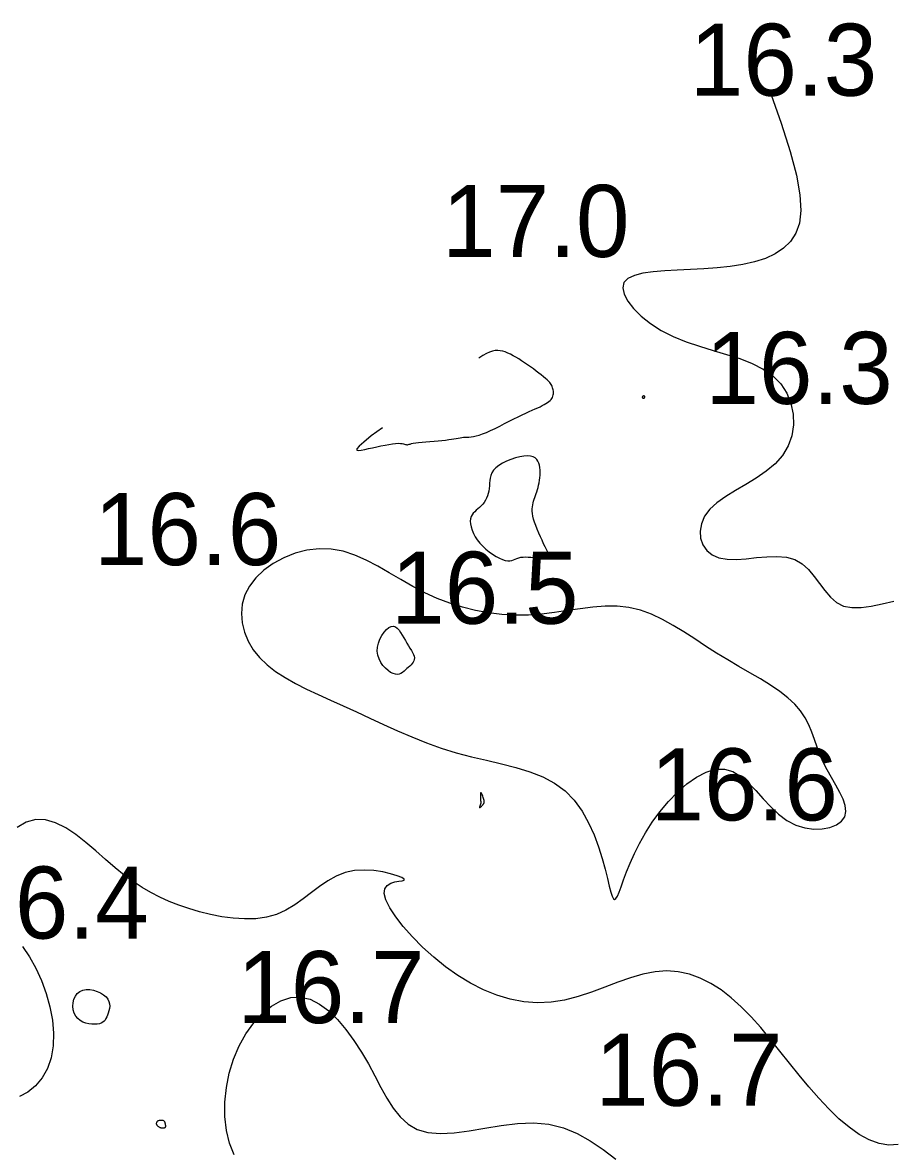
# Model space of a CAD drawing. Extents: x 3040093 to 3056816, y 408076 to 509144.
# Drawn here: x 3045706.9 to 3045767.3, y 434615.2 to 434693.7 of the extents above; entities that cross this region are included whole.
import ezdxf

# ---------------------------------------------------------------- set-up
doc = ezdxf.new("R2010")
doc.units = 0
doc.layers.add('V-CHAN-CONT-EL17', color=7, linetype='Continuous')
doc.layers.add('V-TOPO-SOUN-0610', color=7, linetype='Continuous')

msp = doc.modelspace()

# ---------------------------------------------------------------- linework, layer by layer
at = {"layer": 'V-CHAN-CONT-EL17'}
for points in [[(3045758.774, 434689.031), (3045759.617, 434686.678), (3045760.245, 434684.699), (3045760.671, 434683.056), (3045760.909, 434681.708), (3045760.975, 434680.615), (3045760.881, 434679.736), (3045760.643, 434679.032), (3045760.274, 434678.461), (3045759.788, 434677.99), (3045759.199, 434677.603), (3045758.52, 434677.292), (3045757.765, 434677.047), (3045756.947, 434676.861), (3045756.08, 434676.722), (3045755.177, 434676.623), (3045754.252, 434676.555), (3045753.319, 434676.507), (3045752.404, 434676.467), (3045751.53, 434676.421), (3045750.725, 434676.354), (3045750.013, 434676.254), (3045749.421, 434676.106), (3045748.974, 434675.897), (3045748.698, 434675.613), (3045748.611, 434675.245), (3045748.704, 434674.809), (3045748.961, 434674.323), (3045749.365, 434673.809), (3045749.899, 434673.286), (3045750.547, 434672.775), (3045751.293, 434672.295), (3045752.121, 434671.867), (3045753.011, 434671.504), (3045753.942, 434671.191), (3045754.89, 434670.906), (3045755.83, 434670.627), (3045756.738, 434670.332), (3045757.592, 434670.001), (3045758.365, 434669.61), (3045759.036, 434669.138), (3045759.582, 434668.571), (3045760, 434667.924), (3045760.287, 434667.219), (3045760.443, 434666.479), (3045760.465, 434665.726), (3045760.353, 434664.983), (3045760.105, 434664.273), (3045759.719, 434663.619), (3045759.201, 434663.036), (3045758.579, 434662.515), (3045757.889, 434662.043), (3045757.166, 434661.603), (3045756.447, 434661.182), (3045755.765, 434660.764), (3045755.158, 434660.334), (3045754.659, 434659.878), (3045754.298, 434659.386), (3045754.076, 434658.873), (3045753.986, 434658.36), (3045754.021, 434657.866), (3045754.176, 434657.413), (3045754.445, 434657.02), (3045754.821, 434656.709), (3045755.297, 434656.499), (3045755.866, 434656.403), (3045756.506, 434656.396), (3045757.194, 434656.446), (3045757.909, 434656.518), (3045758.626, 434656.581), (3045759.323, 434656.601), (3045759.978, 434656.545), (3045760.566, 434656.381), (3045761.073, 434656.086), (3045761.512, 434655.687), (3045761.907, 434655.22), (3045762.277, 434654.722), (3045762.645, 434654.23), (3045763.033, 434653.781), (3045763.462, 434653.412), (3045763.955, 434653.159), (3045764.526, 434653.048), (3045765.171, 434653.06), (3045765.878, 434653.161), (3045766.635, 434653.321), (3045767.433, 434653.508)], [(3045731.921, 434665.536), (3045731.154, 434664.964), (3045730.624, 434664.543), (3045730.3, 434664.252), (3045730.151, 434664.071), (3045730.147, 434663.979), (3045730.257, 434663.955), (3045730.449, 434663.978), (3045730.694, 434664.029), (3045730.963, 434664.088), (3045731.246, 434664.15), (3045731.537, 434664.214), (3045731.826, 434664.275), (3045732.109, 434664.331), (3045732.376, 434664.379), (3045732.622, 434664.418), (3045732.839, 434664.443), (3045733.021, 434664.453), (3045733.171, 434664.451), (3045733.292, 434664.439), (3045733.389, 434664.421), (3045733.466, 434664.4), (3045733.526, 434664.379), (3045733.572, 434664.361), (3045733.61, 434664.349), (3045733.644, 434664.347), (3045733.678, 434664.352), (3045733.719, 434664.365), (3045733.773, 434664.383), (3045733.846, 434664.405), (3045733.944, 434664.43), (3045734.072, 434664.456), (3045734.238, 434664.482), (3045734.443, 434664.508), (3045734.682, 434664.532), (3045734.945, 434664.556), (3045735.224, 434664.58), (3045735.509, 434664.604), (3045735.791, 434664.629), (3045736.061, 434664.655), (3045736.309, 434664.682), (3045736.53, 434664.71), (3045736.724, 434664.74), (3045736.896, 434664.768), (3045737.049, 434664.796), (3045737.187, 434664.821), (3045737.315, 434664.843), (3045737.436, 434664.86), (3045737.555, 434664.872), (3045737.675, 434664.878), (3045737.8, 434664.882), (3045737.934, 434664.888), (3045738.081, 434664.9), (3045738.244, 434664.924), (3045738.429, 434664.963), (3045738.638, 434665.021), (3045738.875, 434665.104), (3045739.143, 434665.213), (3045739.437, 434665.345), (3045739.749, 434665.493), (3045740.073, 434665.654), (3045740.402, 434665.82), (3045740.728, 434665.986), (3045741.045, 434666.148), (3045741.346, 434666.297), (3045741.625, 434666.432), (3045741.882, 434666.552), (3045742.119, 434666.659), (3045742.336, 434666.755), (3045742.534, 434666.842), (3045742.715, 434666.922), (3045742.879, 434666.997), (3045743.028, 434667.068), (3045743.163, 434667.138), (3045743.285, 434667.207), (3045743.392, 434667.276), (3045743.487, 434667.345), (3045743.568, 434667.416), (3045743.636, 434667.489), (3045743.692, 434667.564), (3045743.736, 434667.642), (3045743.768, 434667.725), (3045743.788, 434667.809), (3045743.799, 434667.896), (3045743.802, 434667.983), (3045743.796, 434668.07), (3045743.784, 434668.155), (3045743.767, 434668.237), (3045743.746, 434668.316), (3045743.721, 434668.39), (3045743.691, 434668.461), (3045743.652, 434668.532), (3045743.603, 434668.605), (3045743.542, 434668.682), (3045743.464, 434668.765), (3045743.369, 434668.856), (3045743.254, 434668.959), (3045743.117, 434669.073), (3045742.961, 434669.198), (3045742.788, 434669.331), (3045742.603, 434669.471), (3045742.407, 434669.614), (3045742.205, 434669.758), (3045742, 434669.902), (3045741.795, 434670.043), (3045741.592, 434670.179), (3045741.392, 434670.307), (3045741.196, 434670.427), (3045741.004, 434670.537), (3045740.816, 434670.636), (3045740.632, 434670.721), (3045740.453, 434670.792), (3045740.278, 434670.846), (3045740.108, 434670.882), (3045739.937, 434670.897), (3045739.761, 434670.888), (3045739.574, 434670.852), (3045739.372, 434670.785), (3045739.149, 434670.684), (3045738.899, 434670.547), (3045738.618, 434670.37)], [(3045767.736, 434615.782), (3045767.085, 434615.732), (3045766.415, 434615.844), (3045765.729, 434616.1), (3045765.032, 434616.485), (3045764.329, 434616.983), (3045763.624, 434617.577), (3045762.922, 434618.251), (3045762.226, 434618.99), (3045761.542, 434619.777), (3045760.866, 434620.597), (3045760.196, 434621.434), (3045759.53, 434622.273), (3045758.864, 434623.099), (3045758.196, 434623.897), (3045757.523, 434624.651), (3045756.842, 434625.345), (3045756.15, 434625.967), (3045755.447, 434626.51), (3045754.729, 434626.966), (3045753.995, 434627.332), (3045753.243, 434627.601), (3045752.471, 434627.768), (3045751.677, 434627.828), (3045750.859, 434627.775), (3045750.017, 434627.609), (3045749.152, 434627.355), (3045748.267, 434627.042), (3045747.364, 434626.701), (3045746.447, 434626.361), (3045745.519, 434626.053), (3045744.581, 434625.807), (3045743.636, 434625.653), (3045742.689, 434625.615), (3045741.742, 434625.691), (3045740.799, 434625.874), (3045739.866, 434626.156), (3045738.946, 434626.529), (3045738.044, 434626.987), (3045737.163, 434627.521), (3045736.309, 434628.124), (3045735.487, 434628.786), (3045734.713, 434629.487), (3045734.004, 434630.203), (3045733.378, 434630.911), (3045732.852, 434631.588), (3045732.444, 434632.211), (3045732.171, 434632.758), (3045732.051, 434633.205), (3045732.091, 434633.536), (3045732.258, 434633.765), (3045732.506, 434633.914), (3045732.793, 434634.005), (3045733.074, 434634.057), (3045733.305, 434634.093), (3045733.443, 434634.133), (3045733.442, 434634.2), (3045733.271, 434634.307), (3045732.946, 434634.441), (3045732.496, 434634.582), (3045731.947, 434634.708), (3045731.33, 434634.8), (3045730.67, 434634.837), (3045729.998, 434634.798), (3045729.341, 434634.663), (3045728.719, 434634.42), (3045728.129, 434634.087), (3045727.559, 434633.693), (3045726.995, 434633.265), (3045726.427, 434632.829), (3045725.842, 434632.415), (3045725.229, 434632.048), (3045724.575, 434631.757), (3045723.873, 434631.562), (3045723.13, 434631.459), (3045722.359, 434631.437), (3045721.57, 434631.485), (3045720.777, 434631.593), (3045719.989, 434631.748), (3045719.221, 434631.942), (3045718.482, 434632.161), (3045717.782, 434632.399), (3045717.116, 434632.659), (3045716.475, 434632.946), (3045715.851, 434633.266), (3045715.237, 434633.626), (3045714.623, 434634.03), (3045714.002, 434634.485), (3045713.365, 434634.997), (3045712.707, 434635.565), (3045712.029, 434636.16), (3045711.338, 434636.748), (3045710.639, 434637.293), (3045709.936, 434637.76), (3045709.234, 434638.114), (3045708.539, 434638.319), (3045707.857, 434638.342), (3045707.193, 434638.158), (3045706.563, 434637.791)], [(3045706.931, 434629.532), (3045707.412, 434628.818), (3045707.855, 434628.025), (3045708.246, 434627.169), (3045708.575, 434626.268), (3045708.832, 434625.343), (3045709.005, 434624.414), (3045709.084, 434623.502), (3045709.06, 434622.627), (3045708.92, 434621.809), (3045708.66, 434621.068), (3045708.293, 434620.415), (3045707.836, 434619.862), (3045707.307, 434619.422), (3045706.724, 434619.106)], [(3045721.64, 434615.059), (3045721.314, 434615.87), (3045721.098, 434616.765), (3045720.991, 434617.723), (3045720.989, 434618.719), (3045721.09, 434619.73), (3045721.291, 434620.733), (3045721.588, 434621.704), (3045721.978, 434622.622), (3045722.449, 434623.467), (3045722.988, 434624.222), (3045723.582, 434624.868), (3045724.216, 434625.389), (3045724.88, 434625.765), (3045725.558, 434625.98), (3045726.237, 434626.016), (3045726.907, 434625.861), (3045727.562, 434625.534), (3045728.198, 434625.06), (3045728.81, 434624.465), (3045729.395, 434623.773), (3045729.949, 434623.011), (3045730.468, 434622.203), (3045730.949, 434621.374), (3045731.391, 434620.549), (3045731.811, 434619.749), (3045732.232, 434618.995), (3045732.673, 434618.306), (3045733.158, 434617.704), (3045733.706, 434617.207), (3045734.34, 434616.836), (3045735.081, 434616.613), (3045735.942, 434616.546), (3045736.906, 434616.603), (3045737.95, 434616.743), (3045739.047, 434616.922), (3045740.174, 434617.099), (3045741.307, 434617.232), (3045742.42, 434617.277), (3045743.489, 434617.192), (3045744.495, 434616.947), (3045745.448, 434616.556), (3045746.361, 434616.047), (3045747.249, 434615.444), (3045748.127, 434614.775)]]:
    msp.add_lwpolyline(points, dxfattribs=at)
for points in [[(3045750.138, 434667.709), (3045750.13, 434667.719), (3045750.12, 434667.727), (3045750.108, 434667.733), (3045750.095, 434667.738), (3045750.081, 434667.74), (3045750.067, 434667.741), (3045750.052, 434667.739), (3045750.037, 434667.735), (3045750.023, 434667.729), (3045750.01, 434667.721), (3045749.998, 434667.712), (3045749.988, 434667.701), (3045749.979, 434667.69), (3045749.972, 434667.679), (3045749.968, 434667.668), (3045749.967, 434667.657), (3045749.968, 434667.646), (3045749.972, 434667.636), (3045749.977, 434667.626), (3045749.984, 434667.617), (3045749.993, 434667.609), (3045750.002, 434667.602), (3045750.013, 434667.595), (3045750.024, 434667.59), (3045750.035, 434667.586), (3045750.047, 434667.583), (3045750.059, 434667.582), (3045750.071, 434667.583), (3045750.083, 434667.585), (3045750.094, 434667.59), (3045750.105, 434667.597), (3045750.115, 434667.606), (3045750.124, 434667.617), (3045750.132, 434667.629), (3045750.139, 434667.643), (3045750.143, 434667.657), (3045750.146, 434667.671), (3045750.146, 434667.685), (3045750.143, 434667.697)], [(3045743.492, 434656.511), (3045743.51, 434656.523), (3045743.524, 434656.534), (3045743.534, 434656.545), (3045743.541, 434656.556), (3045743.546, 434656.567), (3045743.548, 434656.578), (3045743.548, 434656.589), (3045743.546, 434656.602), (3045743.54, 434656.619), (3045743.529, 434656.646), (3045743.51, 434656.688), (3045743.481, 434656.749), (3045743.44, 434656.833), (3045743.385, 434656.946), (3045743.313, 434657.092), (3045743.224, 434657.273), (3045743.122, 434657.485), (3045743.01, 434657.72), (3045742.895, 434657.97), (3045742.781, 434658.228), (3045742.672, 434658.487), (3045742.573, 434658.74), (3045742.49, 434658.979), (3045742.426, 434659.197), (3045742.38, 434659.397), (3045742.351, 434659.58), (3045742.336, 434659.748), (3045742.335, 434659.904), (3045742.345, 434660.05), (3045742.364, 434660.187), (3045742.392, 434660.319), (3045742.426, 434660.448), (3045742.465, 434660.575), (3045742.507, 434660.701), (3045742.552, 434660.829), (3045742.598, 434660.96), (3045742.644, 434661.096), (3045742.689, 434661.239), (3045742.731, 434661.389), (3045742.77, 434661.549), (3045742.804, 434661.716), (3045742.832, 434661.889), (3045742.854, 434662.065), (3045742.869, 434662.243), (3045742.875, 434662.42), (3045742.871, 434662.595), (3045742.857, 434662.765), (3045742.831, 434662.928), (3045742.79, 434663.081), (3045742.73, 434663.22), (3045742.646, 434663.341), (3045742.536, 434663.442), (3045742.395, 434663.517), (3045742.219, 434663.565), (3045742.004, 434663.581), (3045741.749, 434663.563), (3045741.464, 434663.513), (3045741.161, 434663.435), (3045740.852, 434663.333), (3045740.549, 434663.21), (3045740.265, 434663.069), (3045740.011, 434662.916), (3045739.8, 434662.752), (3045739.641, 434662.582), (3045739.528, 434662.407), (3045739.453, 434662.228), (3045739.408, 434662.046), (3045739.382, 434661.864), (3045739.369, 434661.681), (3045739.359, 434661.499), (3045739.343, 434661.319), (3045739.315, 434661.143), (3045739.274, 434660.972), (3045739.22, 434660.807), (3045739.154, 434660.648), (3045739.077, 434660.498), (3045738.989, 434660.357), (3045738.893, 434660.226), (3045738.787, 434660.107), (3045738.674, 434660), (3045738.558, 434659.901), (3045738.442, 434659.805), (3045738.332, 434659.709), (3045738.233, 434659.606), (3045738.148, 434659.493), (3045738.082, 434659.365), (3045738.04, 434659.217), (3045738.025, 434659.047), (3045738.039, 434658.856), (3045738.08, 434658.649), (3045738.148, 434658.43), (3045738.244, 434658.204), (3045738.366, 434657.974), (3045738.515, 434657.745), (3045738.691, 434657.521), (3045738.891, 434657.306), (3045739.11, 434657.104), (3045739.342, 434656.917), (3045739.58, 434656.749), (3045739.817, 434656.603), (3045740.047, 434656.482), (3045740.263, 434656.39), (3045740.457, 434656.329), (3045740.627, 434656.302), (3045740.774, 434656.303), (3045740.906, 434656.326), (3045741.028, 434656.364), (3045741.146, 434656.412), (3045741.267, 434656.461), (3045741.395, 434656.506), (3045741.537, 434656.54), (3045741.697, 434656.559), (3045741.871, 434656.563), (3045742.054, 434656.556), (3045742.241, 434656.541), (3045742.426, 434656.521), (3045742.604, 434656.499), (3045742.77, 434656.478), (3045742.918, 434656.461), (3045743.044, 434656.451), (3045743.149, 434656.447), (3045743.235, 434656.449), (3045743.306, 434656.454), (3045743.362, 434656.463), (3045743.406, 434656.474), (3045743.442, 434656.486), (3045743.469, 434656.499)], [(3045751.201, 434638.886), (3045751.79, 434639.59), (3045752.418, 434640.242), (3045753.072, 434640.816), (3045753.739, 434641.288), (3045754.404, 434641.633), (3045755.054, 434641.826), (3045755.674, 434641.842), (3045756.256, 434641.669), (3045756.806, 434641.336), (3045757.333, 434640.883), (3045757.85, 434640.352), (3045758.365, 434639.785), (3045758.891, 434639.221), (3045759.436, 434638.703), (3045760.013, 434638.271), (3045760.625, 434637.958), (3045761.254, 434637.762), (3045761.876, 434637.675), (3045762.467, 434637.687), (3045763.002, 434637.787), (3045763.457, 434637.968), (3045763.809, 434638.219), (3045764.032, 434638.532), (3045764.112, 434638.896), (3045764.064, 434639.304), (3045763.915, 434639.751), (3045763.69, 434640.228), (3045763.415, 434640.73), (3045763.115, 434641.25), (3045762.815, 434641.78), (3045762.542, 434642.314), (3045762.312, 434642.845), (3045762.115, 434643.373), (3045761.932, 434643.894), (3045761.745, 434644.407), (3045761.534, 434644.911), (3045761.281, 434645.403), (3045760.967, 434645.883), (3045760.573, 434646.348), (3045760.087, 434646.798), (3045759.517, 434647.237), (3045758.876, 434647.668), (3045758.181, 434648.098), (3045757.444, 434648.531), (3045756.68, 434648.972), (3045755.903, 434649.425), (3045755.128, 434649.895), (3045754.365, 434650.383), (3045753.613, 434650.877), (3045752.866, 434651.361), (3045752.121, 434651.818), (3045751.371, 434652.232), (3045750.612, 434652.587), (3045749.839, 434652.867), (3045749.047, 434653.056), (3045748.232, 434653.143), (3045747.396, 434653.145), (3045746.54, 434653.081), (3045745.668, 434652.973), (3045744.781, 434652.843), (3045743.883, 434652.712), (3045742.975, 434652.6), (3045742.06, 434652.53), (3045741.141, 434652.518), (3045740.221, 434652.568), (3045739.303, 434652.677), (3045738.39, 434652.846), (3045737.487, 434653.072), (3045736.596, 434653.354), (3045735.72, 434653.692), (3045734.864, 434654.084), (3045734.028, 434654.525), (3045733.21, 434654.995), (3045732.403, 434655.471), (3045731.603, 434655.929), (3045730.804, 434656.346), (3045730.002, 434656.698), (3045729.19, 434656.961), (3045728.364, 434657.113), (3045727.522, 434657.135), (3045726.679, 434657.034), (3045725.856, 434656.823), (3045725.07, 434656.513), (3045724.341, 434656.119), (3045723.689, 434655.651), (3045723.133, 434655.122), (3045722.692, 434654.546), (3045722.38, 434653.933), (3045722.196, 434653.296), (3045722.133, 434652.646), (3045722.184, 434651.993), (3045722.342, 434651.349), (3045722.601, 434650.724), (3045722.953, 434650.13), (3045723.393, 434649.578), (3045723.913, 434649.075), (3045724.506, 434648.615), (3045725.165, 434648.189), (3045725.884, 434647.787), (3045726.654, 434647.399), (3045727.47, 434647.016), (3045728.324, 434646.629), (3045729.209, 434646.228), (3045730.119, 434645.806), (3045731.051, 434645.371), (3045732.004, 434644.93), (3045732.978, 434644.493), (3045733.971, 434644.071), (3045734.981, 434643.671), (3045736.007, 434643.304), (3045737.049, 434642.979), (3045738.102, 434642.7), (3045739.154, 434642.45), (3045740.19, 434642.207), (3045741.196, 434641.95), (3045742.156, 434641.655), (3045743.056, 434641.302), (3045743.881, 434640.868), (3045744.616, 434640.331), (3045745.251, 434639.678), (3045745.791, 434638.931), (3045746.244, 434638.122), (3045746.621, 434637.282), (3045746.931, 434636.442), (3045747.182, 434635.634), (3045747.385, 434634.889), (3045747.549, 434634.239), (3045747.682, 434633.708), (3045747.792, 434633.301), (3045747.886, 434633.014), (3045747.971, 434632.845), (3045748.053, 434632.791), (3045748.141, 434632.85), (3045748.24, 434633.02), (3045748.358, 434633.298), (3045748.502, 434633.679), (3045748.676, 434634.152), (3045748.887, 434634.702), (3045749.139, 434635.318), (3045749.438, 434635.984), (3045749.789, 434636.688), (3045750.197, 434637.415), (3045750.667, 434638.153)], [(3045733.526, 434648.72), (3045733.426, 434648.63), (3045733.323, 434648.549), (3045733.214, 434648.481), (3045733.096, 434648.434), (3045732.968, 434648.411), (3045732.827, 434648.42), (3045732.67, 434648.467), (3045732.497, 434648.554), (3045732.315, 434648.68), (3045732.134, 434648.841), (3045731.963, 434649.033), (3045731.812, 434649.251), (3045731.69, 434649.492), (3045731.605, 434649.751), (3045731.568, 434650.024), (3045731.585, 434650.306), (3045731.65, 434650.589), (3045731.753, 434650.862), (3045731.887, 434651.116), (3045732.042, 434651.341), (3045732.208, 434651.527), (3045732.378, 434651.664), (3045732.542, 434651.743), (3045732.693, 434651.756), (3045732.832, 434651.711), (3045732.96, 434651.616), (3045733.08, 434651.483), (3045733.193, 434651.321), (3045733.303, 434651.139), (3045733.411, 434650.947), (3045733.519, 434650.756), (3045733.628, 434650.573), (3045733.736, 434650.401), (3045733.84, 434650.237), (3045733.934, 434650.084), (3045734.015, 434649.94), (3045734.081, 434649.805), (3045734.125, 434649.679), (3045734.146, 434649.562), (3045734.14, 434649.454), (3045734.11, 434649.353), (3045734.059, 434649.257), (3045733.992, 434649.166), (3045733.911, 434649.077), (3045733.82, 434648.99), (3045733.724, 434648.902), (3045733.625, 434648.812)], [(3045738.899, 434639.371), (3045738.916, 434639.392), (3045738.93, 434639.411), (3045738.942, 434639.427), (3045738.952, 434639.441), (3045738.96, 434639.454), (3045738.967, 434639.465), (3045738.975, 434639.477), (3045738.982, 434639.489), (3045738.988, 434639.503), (3045738.994, 434639.521), (3045738.997, 434639.544), (3045738.997, 434639.574), (3045738.993, 434639.612), (3045738.984, 434639.661), (3045738.97, 434639.722), (3045738.95, 434639.796), (3045738.925, 434639.877), (3045738.896, 434639.96), (3045738.866, 434640.04), (3045738.837, 434640.111), (3045738.808, 434640.167), (3045738.783, 434640.202), (3045738.762, 434640.211), (3045738.748, 434640.189), (3045738.738, 434640.142), (3045738.733, 434640.075), (3045738.732, 434639.994), (3045738.734, 434639.905), (3045738.737, 434639.814), (3045738.742, 434639.728), (3045738.746, 434639.651), (3045738.75, 434639.59), (3045738.753, 434639.542), (3045738.754, 434639.505), (3045738.754, 434639.476), (3045738.752, 434639.452), (3045738.748, 434639.431), (3045738.742, 434639.409), (3045738.734, 434639.384), (3045738.723, 434639.353), (3045738.711, 434639.319), (3045738.699, 434639.283), (3045738.688, 434639.249), (3045738.679, 434639.217), (3045738.675, 434639.19), (3045738.675, 434639.171), (3045738.681, 434639.162), (3045738.695, 434639.164), (3045738.715, 434639.176), (3045738.739, 434639.196), (3045738.767, 434639.222), (3045738.796, 434639.252), (3045738.825, 434639.284), (3045738.853, 434639.316), (3045738.878, 434639.345)], [(3045710.523, 434624.9), (3045710.461, 434625.132), (3045710.437, 434625.378), (3045710.453, 434625.627), (3045710.507, 434625.867), (3045710.601, 434626.086), (3045710.734, 434626.272), (3045710.906, 434626.414), (3045711.115, 434626.502), (3045711.353, 434626.54), (3045711.607, 434626.534), (3045711.866, 434626.488), (3045712.12, 434626.41), (3045712.357, 434626.304), (3045712.566, 434626.176), (3045712.736, 434626.033), (3045712.858, 434625.878), (3045712.936, 434625.717), (3045712.976, 434625.551), (3045712.985, 434625.384), (3045712.969, 434625.219), (3045712.935, 434625.058), (3045712.889, 434624.906), (3045712.836, 434624.765), (3045712.783, 434624.636), (3045712.727, 434624.523), (3045712.665, 434624.423), (3045712.592, 434624.337), (3045712.505, 434624.266), (3045712.401, 434624.209), (3045712.276, 434624.167), (3045712.126, 434624.139), (3045711.949, 434624.127), (3045711.753, 434624.132), (3045711.544, 434624.158), (3045711.333, 434624.207), (3045711.127, 434624.282), (3045710.935, 434624.386), (3045710.765, 434624.522), (3045710.625, 434624.693)], [(3045716.254, 434617.302), (3045716.263, 434617.328), (3045716.275, 434617.353), (3045716.291, 434617.377), (3045716.311, 434617.4), (3045716.335, 434617.421), (3045716.364, 434617.439), (3045716.397, 434617.455), (3045716.435, 434617.467), (3045716.476, 434617.476), (3045716.519, 434617.482), (3045716.564, 434617.484), (3045716.607, 434617.482), (3045716.648, 434617.477), (3045716.686, 434617.467), (3045716.719, 434617.454), (3045716.747, 434617.436), (3045716.768, 434617.415), (3045716.786, 434617.391), (3045716.799, 434617.363), (3045716.81, 434617.333), (3045716.819, 434617.301), (3045716.826, 434617.267), (3045716.834, 434617.231), (3045716.841, 434617.195), (3045716.849, 434617.158), (3045716.855, 434617.122), (3045716.859, 434617.086), (3045716.859, 434617.053), (3045716.856, 434617.021), (3045716.849, 434616.993), (3045716.835, 434616.969), (3045716.815, 434616.949), (3045716.79, 434616.933), (3045716.76, 434616.921), (3045716.726, 434616.914), (3045716.689, 434616.911), (3045716.651, 434616.911), (3045716.611, 434616.915), (3045716.571, 434616.923), (3045716.532, 434616.935), (3045716.494, 434616.95), (3045716.458, 434616.967), (3045716.424, 434616.986), (3045716.392, 434617.008), (3045716.362, 434617.03), (3045716.336, 434617.054), (3045716.312, 434617.078), (3045716.293, 434617.102), (3045716.276, 434617.126), (3045716.263, 434617.151), (3045716.254, 434617.175), (3045716.248, 434617.2), (3045716.245, 434617.225), (3045716.245, 434617.25), (3045716.248, 434617.276)]]:
    msp.add_lwpolyline(points, close=True, dxfattribs=at)

# ---------------------------------------------------------------- texts
at = {"layer": 'V-TOPO-SOUN-0610'}
for s, p in [('16.3 ', (3045753.273, 434688.58)), ('17.0 ', (3045736.073, 434677.39)), ('16.3 ', (3045754.353, 434667.19)), ('16.6 ', (3045711.893, 434656)), ('16.5 ', (3045732.533, 434651.93)), ('16.6 ', (3045750.543, 434638.28)), ('16.4 ', (3045702.683, 434630.08)), ('16.7 ', (3045721.843, 434624.21)), ('16.7 ', (3045746.703, 434618.47))]:
    msp.add_text(s, height=5, dxfattribs=at).set_placement(p)

doc.saveas('drawing.dxf')
